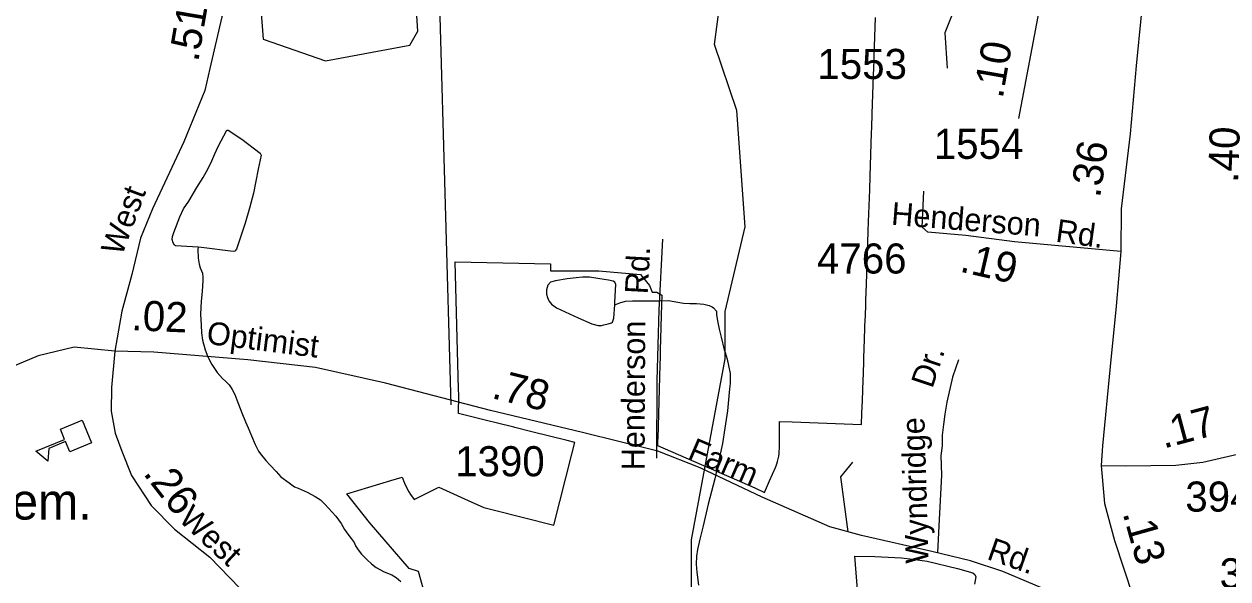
# Model space of a CAD drawing. Extents: x 2001466 to 2224147, y 644118 to 847247.
# Drawn here: x 2071075 to 2076073, y 695337 to 697641 of the extents above; entities that cross this region are included whole.
import ezdxf

# ---------------------------------------------------------------- set-up
doc = ezdxf.new("R2010")
doc.units = 0
for name, color, linetype in [('Exist Boundary Political City Limit New', 7, 'Continuous'), ('Exist Cultural Educational Facility Elementary CELL', 7, 'Continuous'), ('Exist Cultural Educational Facility High Label', 7, 'Continuous'), ('Exist Hydrographic Misc Water Feature', 7, 'Continuous'), ('Exist Road Non-System Type 51', 7, 'Continuous'), ('Exist Road Non-System Type 51 Label', 7, 'Continuous'), ('Exist Road Secondary Mileage Hundredths English Label', 7, 'Continuous'), ('Exist Road Secondary Type 51 Attributed', 7, 'Continuous'), ('Exist Road Secondary Type 51 Label', 7, 'Continuous'), ('Exist Road Secondary Type 51 Number Label', 7, 'Continuous'), ('Map Preparation Boundary City Limit Buffer Line', 7, 'Continuous')]:
    doc.layers.add(name, color=color, linetype=linetype)

msp = doc.modelspace()

# ---------------------------------------------------------------- linework, layer by layer
at = {"layer": 'Exist Boundary Political City Limit New'}
for points in [[(2074599.4, 697347.9), (2074602.1, 697428.1), (2074604.2, 697488.7), (2074604.9, 697508.2), (2074607.6, 697588.2), (2074610.5, 697668)], [(2072749.4, 695232.5), (2072712, 695367.1), (2072673.9, 695379.7), (2072508.8, 695571), (2072414.6, 695690.1), (2072597.4, 695745.2), (2072645.2, 695759.7), (2072654.2, 695734.6), (2072659.6, 695722.3), (2072672.1, 695698.8), (2072679.2, 695687.4), (2072695, 695665.9), (2072796.2, 695718.2), (2072918.9, 695662.9), (2072984.1, 695633.4), (2073022.9, 695623.7), (2073275, 695560.2), (2073349.2, 695855.2), (2073361.5, 695903.6), (2073330.2, 695911.2), (2073256.5, 695929.4), (2073182.8, 695947.8), (2073112.9, 695965.2), (2073108.4, 695966.3), (2073035.5, 695984.5), (2073000.8, 695993.1), (2072961.5, 696002.9), (2072879, 696023.2), (2072879.2, 696100), (2072878.9, 696124.2), (2072864.9, 696653.8), (2073260.6, 696645.8), (2073259.8, 696616.7), (2073461.2, 696616.6), (2073633.5, 696601.1), (2073671.6, 696554.7), (2073683.2, 696528.1), (2073701.5, 696527.6), (2073722.8, 696515.6), (2073721.8, 696477), (2073716.2, 696287), (2073715.2, 696256), (2073714.4, 696227.1), (2073705.6, 695919.2), (2073705.4, 695911.8), (2073704.8, 695890.8), (2074108.8, 695714.6), (2074149.2, 695695.8), (2074170.2, 695743.6), (2074194.2, 695798.8), (2074197.5, 695806.7), (2074200.5, 695815.1), (2074203.5, 695824.7), (2074206.1, 695835.4), (2074208.2, 695846.1), (2074209.8, 695856.1), (2074210.6, 695866), (2074211.1, 695879.4), (2074211.6, 695990.4), (2074263.5, 695988.9), (2074552.1, 695978), (2074553.8, 696025.1), (2074555.6, 696078), (2074558.5, 696163.4), (2074559.4, 696187.2), (2074563.2, 696301.9), (2074564, 696322.8), (2074566.2, 696388), (2074567.8, 696430.2), (2074569.2, 696474.1), (2074569.9, 696493.1), (2074572.2, 696560.1), (2074575.1, 696646.1), (2074578.1, 696732.2), (2074579.9, 696781), (2074581.1, 696819.4), (2074585.8, 696952.4), (2074587.8, 697009.8), (2074593.9, 697189.1), (2074594.6, 697211.3), (2074596.6, 697267.8), (2074599.4, 697347.9)]]:
    msp.add_lwpolyline(points, dxfattribs=at)
at = {"layer": 'Exist Cultural Educational Facility Elementary CELL'}
msp.add_lwpolyline([(2071354.7, 695902), (2071264.2, 695864.4), (2071246.6, 695906.9), (2071177.2, 695878.2), (2071172.9, 695825.4), (2071124.2, 695866.5), (2071242.9, 695915.8), (2071225.3, 695958.3), (2071315.7, 695995.9)], close=True, dxfattribs=at)
at = {"layer": 'Exist Hydrographic Misc Water Feature'}
for points in [[(2073669.2, 694148), (2073914, 694948.9), (2073938, 695115.7), (2073845.9, 695298), (2073845.9, 695498.2), (2073986, 696249.9), (2073986, 696446.8), (2074069, 696799.4), (2074033.9, 697282.4), (2073942.1, 697556.6), (2074016.1, 698122.6), (2074223, 698630.2), (2074223, 698899.3), (2074256, 698941.2)], [(2072326.1, 697487.8), (2072676.1, 697552.8), (2072709.1, 697611.2), (2072700.1, 697762.3), (2072358.1, 697985.8), (2072366.1, 698185.8), (2072241.2, 698270.4), (2072125.1, 698203.8), (2072033.1, 698028.6), (2072068.1, 697578.4), (2072326.1, 697487.8)], [(2071797.2, 696714.1), (2071703.3, 696720.2), (2071699, 696722.1), (2071693.1, 696731.9), (2071689, 696745.9), (2071691, 696758.2), (2071697, 696775.9), (2071720.8, 696840), (2071737.2, 696874.1), (2071759.1, 696906), (2071792.7, 696962.2), (2071818.8, 697004.1), (2071838.9, 697040.4), (2071854.9, 697072.4), (2071866.6, 697102.3), (2071880.5, 697132.2), (2071916.4, 697200.2), (2071922.5, 697200.5), (2071978.5, 697162.4), (2072054.4, 697104.6), (2072058.7, 697096.7), (2072046.4, 697038.5), (2072026.7, 696938.5), (2072010.9, 696876.4), (2071992.9, 696814.6), (2071957, 696706.5), (2071949.2, 696698.3), (2071943, 696696.4), (2071811.4, 696712.3), (2071797.2, 696714.1)], [(2071797.2, 696714.1), (2071795.6, 696704.2), (2071797.2, 696668.2), (2071801.3, 696644.1), (2071805.4, 696628.5), (2071811.4, 696616.2), (2071815.3, 696606.3), (2071817.3, 696590.1), (2071817.5, 696576.3), (2071813.6, 696530.2), (2071809.5, 696490.3), (2071807.9, 696436.2), (2071810, 696390.1), (2071811.8, 696358.2), (2071815.7, 696328.4), (2071826.2, 696288.2), (2071838, 696258.5), (2071854, 696226.4), (2071876.4, 696194.3), (2071897.9, 696168.6), (2071912.1, 696156.4), (2071926.4, 696142.4), (2071934.2, 696130.8), (2071938.3, 696122.8), (2071950.4, 696102.7), (2071958.6, 696080.8), (2071978.5, 696026.7), (2071994.7, 695988.9), (2072004.8, 695964.7), (2072018.7, 695930.9), (2072034.7, 695894.8), (2072048.6, 695866.7), (2072054.8, 695856.9), (2072079, 695828.9), (2072096.8, 695809.1), (2072121, 695782.8), (2072140.7, 695761.1), (2072175.2, 695735.3), (2072197.1, 695719.3), (2072213.1, 695713.3), (2072250.8, 695697.4), (2072283, 695679.1), (2072305, 695665.3), (2072323.2, 695647.5), (2072368.9, 695597.6), (2072391.1, 695567.4), (2072405.2, 695541.8), (2072419.2, 695521.8), (2072433.3, 695503.9), (2072445.4, 695487.8), (2072451.2, 695473.6), (2072461.2, 695457.8), (2072475.3, 695439.9), (2072499.8, 695415.9), (2072517.4, 695399.8), (2072537.3, 695383.9), (2072569.7, 695366), (2072601.7, 695353.8), (2072619.7, 695342.2), (2072639.6, 695326.2)], [(2073527.3, 696475.4), (2073527.3, 696485.5), (2073531.2, 696559.6), (2073527.3, 696569.5), (2073521.1, 696573.3), (2073501.4, 696577.5), (2073464.9, 696583.4), (2073422.9, 696589.4), (2073393.2, 696589.4), (2073366.9, 696587.3), (2073329.4, 696583.3), (2073281.2, 696575.2), (2073261.1, 696568.8), (2073249.2, 696556.9), (2073243.5, 696537.1), (2073243.3, 696518.8), (2073247.4, 696504.8), (2073253.1, 696491), (2073265.2, 696477), (2073285.5, 696462.9), (2073321.6, 696445.3), (2073375.5, 696421.3), (2073431.5, 696395.4), (2073457.8, 696389.4), (2073471.7, 696389.3), (2073481.3, 696391.5), (2073499.6, 696395.6), (2073513.3, 696399.6), (2073517.4, 696403.5), (2073523.6, 696419.6), (2073527.3, 696475.4)], [(2073527.3, 696475.4), (2073549, 696483.4), (2073571.4, 696489.8), (2073601.3, 696491.7), (2073651.1, 696491.9), (2073709.4, 696492), (2073751, 696492.2), (2073789.1, 696486), (2073813.1, 696482), (2073839.2, 696480.1), (2073867.2, 696480.3), (2073897, 696478.2), (2073919.5, 696472.3), (2073931.2, 696466.1), (2073937.4, 696462.3), (2073949.5, 696448.3)], [(2073949.5, 696448.3), (2073949.3, 696434.1), (2073953.4, 696408.3), (2073961.4, 696374.3), (2073969.4, 696340.3), (2073981.5, 696288.5), (2073985.4, 696276.5), (2073993.6, 696248.6), (2073999.9, 696222.5), (2074005.9, 696190.3), (2074005.9, 696148.5), (2074003.8, 696126.6), (2073996, 696034.4), (2073984.1, 695962.4), (2073974.3, 695898.6), (2073962.4, 695842.4), (2073942.3, 695752.5), (2073914.8, 695646.4), (2073894.7, 695556.6), (2073881, 695502.3), (2073871.1, 695458.3), (2073867, 695430.6), (2073865, 695398.4), (2073867.4, 695364.4), (2073875.4, 695310.4)], [(2074534.7, 695293.3), (2074524.6, 695431.1), (2074606.5, 695429.6), (2074718.4, 695423.6), (2074764.1, 695417.9), (2074824.6, 695409.9), (2074950.5, 695380.3), (2075014.3, 695362.5), (2075022.3, 695354.8), (2075026.6, 695344.8), (2075020.9, 695314.9)]]:
    msp.add_lwpolyline(points, dxfattribs=at)
at = {"layer": 'Exist Road Non-System Type 51'}
for points in [[(2071978, 698723.1), (2072149.8, 698706.3), (2072225.5, 698692.7), (2072283.2, 698677.5), (2072320.9, 698664.8), (2072376.5, 698645.6), (2072459.7, 698605.9), (2072501.3, 698583.1), (2072540.6, 698550.3), (2072575.9, 698517.6), (2072603.2, 698481), (2072624.6, 698454.6), (2072649.6, 698404.1), (2072710.9, 698127.8), (2072797.3, 697801), (2072799.7, 697721), (2072846.1, 696060.2)], [(2073725.8, 696748.1), (2073709.8, 696454.4), (2073701.8, 696160.6), (2073700.4, 695837.4)], [(2074954, 696246.1), (2074930.1, 696174.6), (2074906.2, 696071.1), (2074897.2, 696021.3), (2074892.3, 695977.4), (2074887.4, 695933.5), (2074886.5, 695889.5), (2074881.7, 695849.6), (2074884, 695767.6), (2074873.5, 695557.2), (2074867.9, 695444.7)], [(2074515, 695821.3), (2074465.2, 695760.3), (2074495.2, 695532.2)]]:
    msp.add_lwpolyline(points, dxfattribs=at)
at = {"layer": 'Exist Road Secondary Type 51 Attributed'}
for points in [[(2071993.3, 699020.5), (2071982, 698840.1), (2071972.1, 698548.6), (2071953.8, 698191.1), (2071952.6, 697933.1), (2071936.3, 697817.6), (2071895.7, 697671.1), (2071845.6, 697456.1), (2071824.9, 697365.3), (2071738.5, 697151.9), (2071608, 696873.2), (2071558.7, 696752.1), (2071521.7, 696600.8), (2071480.7, 696448), (2071451.7, 696282.8)], [(2075293.1, 697723.6), (2075154.7, 697752.3), (2075054.4, 697765), (2074987.6, 697742.8), (2074933.5, 697695), (2074898.4, 697604.2), (2074908, 697457.7)], [(2075293.1, 697723.6), (2075204, 697249)], [(2075712.5, 697677.5), (2075691.8, 697467.2), (2075667.9, 697185.3), (2075630.5, 696873.2), (2075628.9, 696696.4)], [(2075628.9, 696696.4), (2075186.5, 696736.2), (2074985.2, 696763.3), (2074827.6, 696776), (2074803.7, 696796.7), (2074810.1, 696946.4)], [(2075628.9, 696696.4), (2075609.8, 696468.7), (2075584.4, 696218.6), (2075551.8, 695888.9), (2075547, 695807.7)], [(2071451.7, 696282.8), (2071283, 696299.5), (2071133, 696263.1), (2070901.9, 696166.8), (2070643.1, 696087.9), (2070475.8, 696068.9), (2070292.8, 696078.4), (2070109.7, 696097.3), (2069898.3, 696087.9), (2069524.3, 696037.3), (2069219.7, 695988.4), (2069038.3, 695990), (2068650.9, 696040.5), (2068546.8, 696058.9), (2068425.2, 696078)], [(2071451.7, 696282.8), (2071437.7, 696132.2), (2071436.1, 696032.7), (2071453.5, 695941.2), (2071480.3, 695866.9), (2071521.3, 695765.9), (2071603, 695641.9), (2071699.3, 695543.2), (2071846, 695427.2), (2071970.7, 695297.7), (2072074.8, 695147.7), (2072077.3, 695143.2)], [(2075397.9, 695258.1), (2075138, 695367), (2075004.2, 695411.2), (2074843.3, 695450.7), (2074551.4, 695517), (2074419.6, 695552.6), (2074139.1, 695675.7), (2073881.9, 695797.3), (2073706.7, 695866.8), (2073393.5, 695945), (2073011.2, 696036.6), (2072575.7, 696150.2), (2072284.6, 696215), (2072003.7, 696246.6), (2071613.9, 696278.9), (2071451.7, 696282.8)], [(2075547, 695807.7), (2075648.8, 695806.1), (2075857.3, 695809.3), (2075968.7, 695822), (2076148.6, 695863.5), (2076347.5, 695928.8), (2076477.6, 695975.7)], [(2075547, 695807.7), (2075561.3, 695650), (2075602.7, 695495.6), (2075716.7, 695146.7)]]:
    msp.add_lwpolyline(points, dxfattribs=at)
at = {"layer": 'Map Preparation Boundary City Limit Buffer Line'}
for points in [[(2074599.4, 697347.9), (2074602.1, 697428.1), (2074604.2, 697488.7), (2074604.9, 697508.2), (2074607.6, 697588.2), (2074610.5, 697668)], [(2072749.4, 695232.5), (2072712, 695367.1), (2072673.9, 695379.7), (2072508.8, 695571), (2072414.6, 695690.1), (2072597.4, 695745.2), (2072645.2, 695759.7), (2072654.2, 695734.6), (2072659.6, 695722.3), (2072672.1, 695698.8), (2072679.2, 695687.4), (2072695, 695665.9), (2072796.2, 695718.2), (2072918.9, 695662.9), (2072984.1, 695633.4), (2073022.9, 695623.7), (2073275, 695560.2), (2073349.2, 695855.2), (2073361.5, 695903.6), (2073330.2, 695911.2), (2073256.5, 695929.4), (2073182.8, 695947.8), (2073112.9, 695965.2), (2073108.4, 695966.3), (2073035.5, 695984.5), (2073000.8, 695993.1), (2072961.5, 696002.9), (2072879, 696023.2), (2072879.2, 696100), (2072878.9, 696124.2), (2072864.9, 696653.8), (2073260.6, 696645.8), (2073259.8, 696616.7), (2073461.2, 696616.6), (2073633.5, 696601.1), (2073671.6, 696554.7), (2073683.2, 696528.1), (2073701.5, 696527.6), (2073722.8, 696515.6), (2073721.8, 696477), (2073716.2, 696287), (2073715.2, 696256), (2073714.4, 696227.1), (2073705.6, 695919.2), (2073705.4, 695911.8), (2073704.8, 695890.8), (2074108.8, 695714.6), (2074149.2, 695695.8), (2074170.2, 695743.6), (2074194.2, 695798.8), (2074197.5, 695806.7), (2074200.5, 695815.1), (2074203.5, 695824.7), (2074206.1, 695835.4), (2074208.2, 695846.1), (2074209.8, 695856.1), (2074210.6, 695866), (2074211.1, 695879.4), (2074211.6, 695990.4), (2074263.5, 695988.9), (2074552.1, 695978), (2074553.8, 696025.1), (2074555.6, 696078), (2074558.5, 696163.4), (2074559.4, 696187.2), (2074563.2, 696301.9), (2074564, 696322.8), (2074566.2, 696388), (2074567.8, 696430.2), (2074569.2, 696474.1), (2074569.9, 696493.1), (2074572.2, 696560.1), (2074575.1, 696646.1), (2074578.1, 696732.2), (2074579.9, 696781), (2074581.1, 696819.4), (2074585.8, 696952.4), (2074587.8, 697009.8), (2074593.9, 697189.1), (2074594.6, 697211.3), (2074596.6, 697267.8), (2074599.4, 697347.9)]]:
    msp.add_lwpolyline(points, dxfattribs=at)

# ---------------------------------------------------------------- texts
at = {"layer": 'Exist Cultural Educational Facility High Label'}
msp.add_text('West Lake Elem.', height=150, dxfattribs=at).set_placement((2069839.7, 695583.2))
at = {"layer": 'Exist Road Non-System Type 51 Label'}
for s, rotation, p in [('Rd.', 86.8814, (2073663.9, 696517.5)), ('Henderson', 89.7516, (2073651, 695787.6)), ('Dr.', 71.5723, (2074845.7, 696124.1)), ('Wyndridge', 91.6217, (2074830.1, 695402.2)), ('West', 317.1619, (2071711.4, 695580.9))]:
    msp.add_text(s, height=95, rotation=rotation, dxfattribs=at).set_placement(p)
at = {"layer": 'Exist Road Secondary Mileage Hundredths English Label'}
for s, rotation, p in [('.51', 80.297, (2071797.4, 697480.9)), ('.10', 80.101, (2075137.7, 697328.5)), ('.40', 88.0237, (2076115.1, 696980.8)), ('.36', 81.5243, (2075542, 696916.6)), ('.19', 347.0107, (2074955.8, 696613.7)), ('.02', 357.5391, (2071518.9, 696369.6)), ('.78', 346.0375, (2073011.9, 696088.2)), ('.17', 14.9218, (2075806.5, 695877.3)), ('.26', 307.7274, (2071566.3, 695774.1)), ('.13', 285.687, (2075635.5, 695609.5))]:
    msp.add_text(s, height=125, rotation=rotation, dxfattribs=at).set_placement(p)
at = {"layer": 'Exist Road Secondary Type 51 Label'}
for s, rotation, p in [('West', 69.4694, (2071480.6, 696674.2)), ('Henderson', 355.4841, (2074673, 696807.4)), ('Rd.', 352.0135, (2075354.7, 696737.6)), ('Optimist', 352.8871, (2071829.4, 696312.9)), ('Farm', 336.7791, (2073824.9, 695837.5)), ('Rd.', 340.608, (2075068.1, 695420.2))]:
    msp.add_text(s, height=95, rotation=rotation, dxfattribs=at).set_placement(p)
at = {"layer": 'Exist Road Secondary Type 51 Number Label'}
for s, p in [('1553', (2074368.7, 697412.8)), ('1554', (2074852, 697081)), ('4766', (2074366.8, 696604.8)), ('1390', (2072864.7, 695762.8)), ('3942', (2075896.3, 695616)), ('3943', (2076038.8, 695297.3))]:
    msp.add_text(s, height=125, dxfattribs=at).set_placement(p)

doc.saveas('drawing.dxf')
